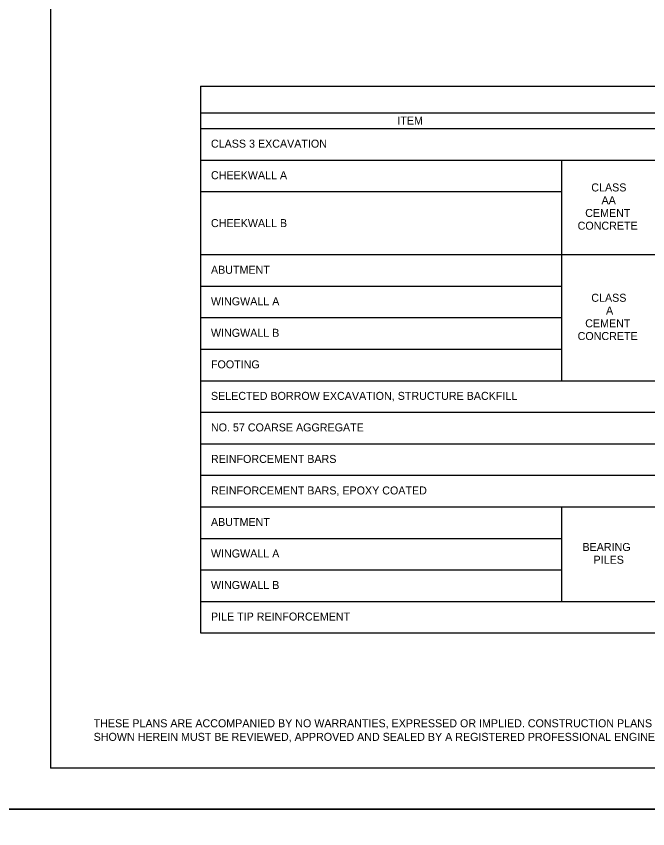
# Model space of a CAD drawing. Extents: x -5022 to -159, y 1126 to 7226.
# Drawn here: x -1290 to -1053.3, y 3494.5 to 3798.9 of the extents above; entities that cross this region are included whole.
import ezdxf

# ---------------------------------------------------------------- set-up
doc = ezdxf.new("R2010")
doc.units = 0
for name, color, linetype in [('2', 7, 'Continuous'), ('3', 7, 'Continuous'), ('9', 7, 'Continuous'), ('PLT-BNDY', 7, 'Continuous')]:
    doc.layers.add(name, color=color, linetype=linetype)

msp = doc.modelspace()

# ---------------------------------------------------------------- linework, layer by layer
at = {"layer": '2'}
for p in [(-1277.13, 4081.14), (-491.13, 3517.14)]:
    msp.add_line(p, (-1277.13, 3517.14), dxfattribs=at)
at = {"layer": '9'}
for p, q in [((-1220.93, 3772.66), (-756.56, 3772.66)), ((-1220.93, 3772.66), (-1220.93, 3567.85)), ((-1220.93, 3762.73), (-756.56, 3762.73)), ((-1220.93, 3756.83), (-756.56, 3756.83)), ((-1220.93, 3745.02), (-756.56, 3745.02)), ((-1085.7, 3745.02), (-1085.7, 3662.34)), ((-1220.93, 3733.21), (-1085.7, 3733.21)), ((-1220.93, 3709.59), (-756.56, 3709.59)), ((-1220.93, 3697.77), (-1085.7, 3697.77)), ((-1220.93, 3685.96), (-1085.7, 3685.96)), ((-1220.93, 3674.15), (-1085.7, 3674.15)), ((-1220.93, 3662.34), (-756.56, 3662.34)), ((-1220.93, 3650.53), (-756.56, 3650.53)), ((-1220.93, 3638.72), (-756.56, 3638.72)), ((-1220.93, 3626.91), (-756.56, 3626.91)), ((-1220.93, 3615.09), (-756.56, 3615.09)), ((-1085.7, 3615.09), (-1085.7, 3579.66)), ((-1220.93, 3603.28), (-1085.7, 3603.28)), ((-1220.93, 3591.47), (-1085.7, 3591.47)), ((-1220.93, 3579.66), (-756.56, 3579.66)), ((-1220.93, 3567.85), (-756.56, 3567.85))]:
    msp.add_line(p, q, dxfattribs=at)
at = {"layer": 'PLT-BNDY'}
for points in [[(-1317.13, 4095.81), (-476.13, 4095.81), (-476.13, 3501.81), (-1317.13, 3501.81)], [(-1317.13, 3501.81), (-476.13, 3501.81), (-476.13, 2907.81), (-1317.13, 2907.81)]]:
    msp.add_lwpolyline(points, close=True, dxfattribs=at)

# ---------------------------------------------------------------- texts
at = {"layer": '2'}
for s, p in [('THESE PLANS ARE ACCOMPANIED BY NO WARRANTIES, EXPRESSED OR IMPLIED. CONSTRUCTION PLANS PREPARED FROM DESIGN AND DETAIL INFORMATION', (-1261, 3532.49)), ('SHOWN HEREIN MUST BE REVIEWED, APPROVED AND SEALED BY A REGISTERED PROFESSIONAL ENGINEER FOR EACH SPECIFIC PROJECT.', (-1261, 3527.4))]:
    msp.add_text(s, height=3.00008, dxfattribs=at).set_placement(p)
at = {"layer": '3'}
for s, height, p in [('ITEM', 3, (-1147.16, 3758.31)), ('CLASS 3 EXCAVATION', 3.0001, (-1217.03, 3749.65)), ('CHEEKWALL A', 3.0001, (-1217.03, 3737.83)), ('CLASS', 3, (-1074.47, 3733.25)), ('AA', 3, (-1070.64, 3728.47)), ('CEMENT', 3, (-1076.75, 3723.69)), ('CHEEKWALL B', 3.0001, (-1217.03, 3719.89)), ('CONCRETE', 3, (-1079.59, 3718.91)), ('ABUTMENT', 3, (-1217.03, 3702.4)), ('WINGWALL A', 3, (-1217.03, 3690.59)), ('CLASS', 3, (-1074.47, 3691.91)), ('A', 3, (-1068.95, 3687.13)), ('CEMENT', 3, (-1076.75, 3682.35)), ('WINGWALL B', 3, (-1217.03, 3678.78)), ('CONCRETE', 3, (-1079.59, 3677.57)), ('FOOTING', 3, (-1217.03, 3666.97)), ('SELECTED BORROW EXCAVATION, STRUCTURE BACKFILL', 3.0001, (-1217.03, 3655.15)), ('NO. 57 COARSE AGGREGATE', 3.0001, (-1217.03, 3643.34)), ('REINFORCEMENT BARS', 3.0001, (-1217.03, 3631.53)), ('REINFORCEMENT BARS, EPOXY COATED', 3.0001, (-1217.03, 3619.72)), ('ABUTMENT', 3, (-1217.03, 3607.91)), ('BEARING', 3, (-1077.78, 3598.54)), ('WINGWALL A', 3, (-1217.03, 3596.1)), ('PILES', 3, (-1073.62, 3593.76)), ('WINGWALL B', 3, (-1217.03, 3584.29)), ('PILE TIP REINFORCEMENT', 3.0001, (-1217.03, 3572.47))]:
    msp.add_text(s, height=height, dxfattribs=at).set_placement(p)

doc.saveas('drawing.dxf')
